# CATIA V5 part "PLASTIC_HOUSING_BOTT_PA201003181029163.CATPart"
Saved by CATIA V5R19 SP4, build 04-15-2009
Part number: PLASTIC_HOUSING_BOTT_PA201003181029163
Bounding box of the stored display mesh (mm): x -26 to 26, y -20.64 to 95, z 0 to 11
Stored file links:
  E:\CadInnWork\1\PLASTIC_HOUSING_BOTT_PA201003181029163.CATPart
  C:\Documents and Settings\moren\Bureau\3D models\Lampe\CATIA_V5\plastic_housing_up.CATPart
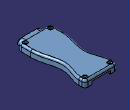
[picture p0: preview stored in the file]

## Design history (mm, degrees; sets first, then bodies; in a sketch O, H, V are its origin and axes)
Parameters
  Update = false
  PDM_version = "A"
  PDM_iteration = 1
  PDM_owner = "moren                    "
  PDM_comment = ""
  PDM_partnumber = "PA002170EA6A57201003181029160003"
Body1 (main body)
  Body2
    Solid1: solid without history
    Sketch1 on xy-plane, origin (0, 0, 0), H (1, 0, 0), V (0, 1, 0)
      line L1 (-40.7243, 108.5502) -> (41.8092, 108.5502)
      line L2 (41.8092, 108.5502) -> (41.8092, -35.0377)
      line L3 (41.8092, -35.0377) -> (-40.7243, -35.0377)
      line L4 (-40.7243, -35.0377) -> (-40.7243, 108.5502)
      horizontal: L1 H, L3 H
      vertical: L2 V, L4 V
    Pocket1: profile Sketch1, direction (0, 0, -1), through (limit type 3)
    Sketch2 on face of Solid1, origin (-15.025, 0, 0), H (0, 1, 0), V (0, 0, 1)
      point P1 (95, 0)
      line L1 (95, 0) -> (93.875, 0)
      line L2 (93.875, 0) -> (93.875, 0.75)
      line L3 (93.875, 0.75) -> (95, 0.75)
      line L4 (95, 0.75) -> (95, 0)
      reference projected point E1 (95, 0) from Sketch3.P17
      reference projected line E2 (93, 0) -> (93, 5.525) from edge [face of Solid1 | face of Solid1]
      length L4 = 0.75
      distance L2 E2 = 0.875
      horizontal: L1 H, L3 H
      vertical: L2 V, L4 V
      coincidence: P1 E1
    Sketch3 on xy-plane, origin (0, 0, 0), H (1, 0, 0), V (0, 1, 0)
      projected line E1 (-18.9, -12.64) -> (-18.9, -19.64) from edge [face of Solid1 | face of Solid1]
      projected arc E2 centre (-19.4001, -12.6401) radius 0.5001 from (-18.9, -12.64) to (-19.4, -12.14) ccw from edge [face of Solid1 | face of Solid1]
      projected line E3 (-19.4, -12.14) -> (-21, -12.14) from edge [face of Solid1 | face of Solid1]
      projected arc E4 centre (-21, -7.14) radius 5 from (-26, -7.14) to (-21, -12.14) ccw from edge [face of Solid1 | face of Solid1]
      projected line E5 (-26, 8.6583) -> (-26, -7.14) from edge [face of Solid1 | face of Solid1]
      projected curve E6 from edge [face of Solid1 | face of Solid1]
      projected line E7 (-26, 90) -> (-26, 85.2347) from edge [face of Solid1 | face of Solid1]
      projected arc E8 centre (-21, 90) radius 5 from (-21, 95) to (-26, 90) ccw from edge [face of Solid1 | face of Solid1]
      projected line E9 (-15.025, 95) -> (-21, 95) from edge [face of Solid1 | face of Solid1]
      point P17 (-15.025, 95)
      line L1 (-18.9, -19.64) -> (-18.9, -22.3506)
      tangency: L1 E2
    Slot1: profile Sketch2, centre curve Sketch3
    Mirror1: of Slot1, about yz-plane
    Point1: type Center, Curve edge [face of Solid1 | face of Solid1]
    Plane1: type OffsetPt, RefPlane yz-plane, RefPoint Point1
    Sketch4 on face of Solid1, origin (20.4668, -2.0655, 11), H (1, 0, 0), V (0, 1, 0)
      point P1 (-0.4668, -4.0745)
      reference projected point E1 (-0.4668, -4.0745) from Point1
      coincidence: P1 E1
    Hole1: placed by Sketch4, at (20, -6.14, 11) direction (0, 0, -1), diameter 6, depth 3
    Sketch5 on face of Hole1, origin (0, 0, 8), H (1, 0, 0), V (0, 1, 0)
      circle A1 centre (20, -6.14) radius 2
      point P1 (20, -6.14)
      reference projected point E1 (20, -6.14) from Point1
      projected circle E2 centre (20, -6.14) radius 2.4 from edge [face of Solid1 | face of Hole1]
      radius A1 = 2
      coincidence: P1 E1
    Pad1: profile Sketch5, direction (0, 0, -1), up to face of Solid1
    Mirror2: of Hole1, Pad1, about yz-plane
    Point2: type Center, Curve edge [face of Solid1 | face of Solid1]
    Sketch6 on face of Solid1, origin (16.6497, 85.0207, 11), H (1, 0, 0), V (0, 1, 0)
      point P1 (3.3503, 3.9793)
      reference projected point E1 (3.3503, 3.9793) from Point2
      coincidence: P1 E1
    Hole2: placed by Sketch6, at (20, 89, 11) direction (0, 0, -1), diameter 6, depth 3
    Sketch7 on face of Hole2, origin (0, 0, 8), H (1, 0, 0), V (0, 1, 0)
      circle A1 centre (20, 89) radius 2
      point P1 (20, 89)
      reference projected point E1 (20, 89) from Point2
      projected circle E2 centre (20, 89) radius 2.4 from edge [face of Solid1 | face of Hole2]
      radius A1 = 2
      coincidence: P1 E1
    Pad2: profile Sketch7, direction (0, 0, -1), up to face of Solid1
    Mirror3: of Hole2, Pad2, about yz-plane
    Fillet1: radius 0.5, on edge [face of Hole2 | face of Solid1]; edge [face of Mirror3 | face of Solid1]; edge [face of Mirror2 | face of Solid1]; edge [face of Hole1 | face of Solid1]
  Add1: tool Body2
